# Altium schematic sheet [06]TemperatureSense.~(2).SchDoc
size A4; SheetNumber: 1; SheetTotal: 4
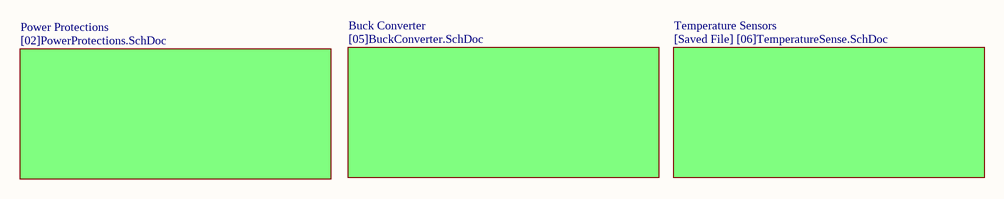
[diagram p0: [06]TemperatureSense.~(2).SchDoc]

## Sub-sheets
Buck Converter = [05]BuckConverter.SchDoc: no entries
Power Protections = [02]PowerProtections.SchDoc: no entries
Temperature Sensors = [Saved File] [06]TemperatureSense.SchDoc: no entries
